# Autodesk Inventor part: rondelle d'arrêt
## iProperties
Created: 2002-06
Part Number: rondelle d'arrêt
Material: Par défaut
Document SubType Name: Modélisation
Designer: REVEST Pierre
Control State: 0
Master: False
Checked Out: False
Shininess: 21.0
Length Units: 11269
Angle Units: 11279
Time Units: 11290
Mass Units: 11283
Length Display Precision: 3
Angle Display Precision: 2
Density: 0.0
Volumn: 0.0
Area: 0.0
PropertySet Name: Model Information
Author: REVEST Pierre
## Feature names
1. Extrusion2
